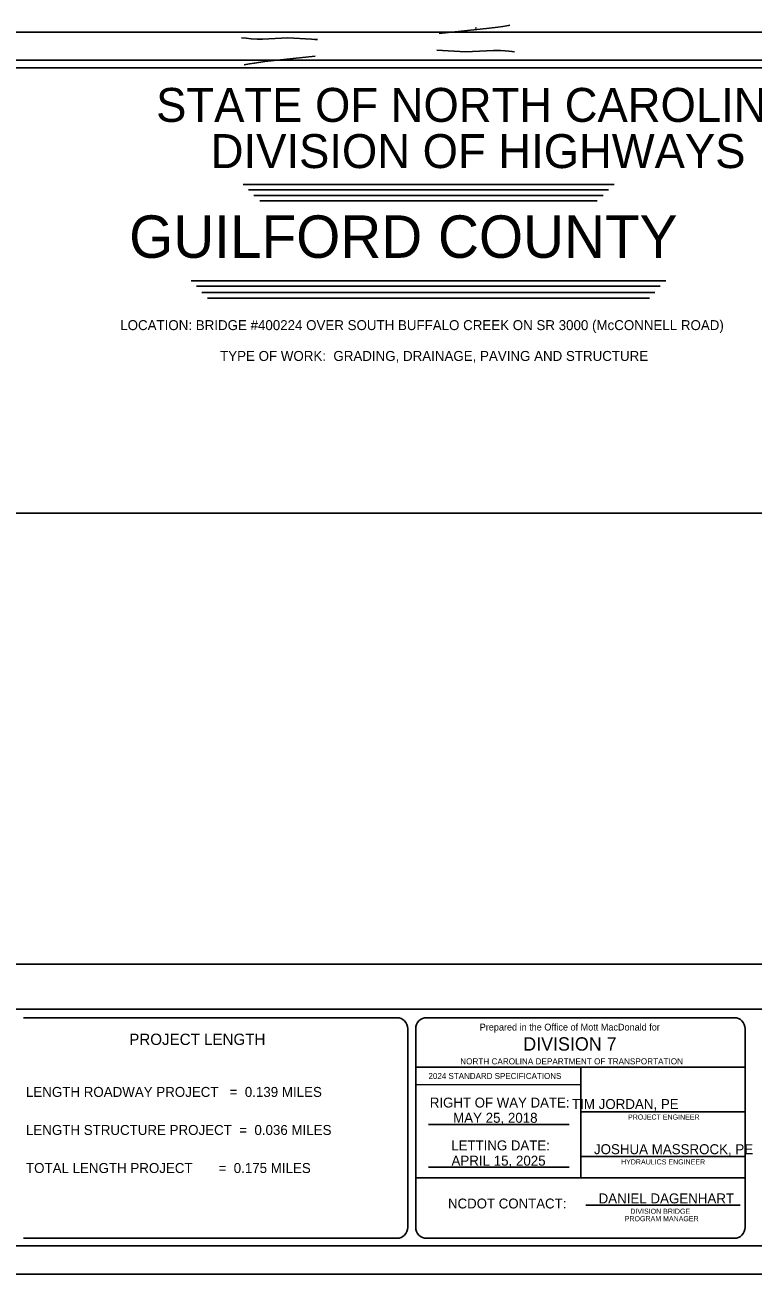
# Model space of a CAD drawing. Extents: x 2538775 to 2540487, y 826823 to 827953.
# Drawn here: x 2539375 to 2540020, y 826847 to 827953 of the extents above; entities that cross this region are included whole.
import ezdxf

# ---------------------------------------------------------------- set-up
doc = ezdxf.new("R2010")
doc.units = 0
for name, color, linetype in [('Old_Level_1', 7, 'Continuous'), ('Old_Level_23', 7, 'Continuous'), ('Old_Level_38', 7, 'Continuous'), ('Old_Level_40', 7, 'Continuous'), ('Old_Level_42', 7, 'Continuous'), ('Old_Level_62', 7, 'Continuous'), ('Old_Level_63', 7, 'Continuous'), ('Sheet Title CELL', 7, 'Continuous')]:
    doc.layers.add(name, color=color, linetype=linetype)

msp = doc.modelspace()

# ---------------------------------------------------------------- linework, layer by layer
at = {"layer": 'Old_Level_1'}
msp.add_lwpolyline([(2539256.9, 827520.8), (2540207.7, 827520.8), (2540207.7, 827121.2), (2539256.9, 827121.2)], close=True, dxfattribs=at)
at = {"layer": 'Old_Level_23'}
for points in [[(2539742.5, 827945.6), (2539787.1, 827950.3), (2539794.4, 827951.1), (2539798.8, 827951.7), (2539802.1, 827952.3), (2539803.7, 827952.6), (2539805.1, 827953)], [(2539775.5, 827950.4), (2539774.3, 827950.2)], [(2539567.2, 827941.7), (2539571.3, 827941.3), (2539575.9, 827940.9), (2539581.2, 827940.6), (2539585.7, 827940.6), (2539608.3, 827941.7), (2539629.3, 827940.4), (2539632.2, 827940.2), (2539634.6, 827940.2)], [(2539632.4, 827925.3), (2539587.8, 827920.6), (2539578.7, 827919.3), (2539574.2, 827918.5), (2539569.5, 827917.7)], [(2539809, 827929.2), (2539806.8, 827929.6), (2539804, 827929.9), (2539800.7, 827930.1), (2539796.8, 827930.3), (2539790.4, 827930.3), (2539765.7, 827929.2), (2539740.3, 827930.7)]]:
    msp.add_lwpolyline(points, dxfattribs=at)
at = {"layer": 'Old_Level_40'}
for p, q in [((2539568.6, 827811.9), (2539897.3, 827811.9)), ((2539573.4, 827807), (2539892.4, 827807)), ((2539578.2, 827802.1), (2539887.6, 827802.1)), ((2539583.5, 827797.2), (2539882.2, 827797.2)), ((2539522.5, 827726.5), (2539943.1, 827726.5)), ((2539527.4, 827721.6), (2539938.3, 827721.6)), ((2539532.2, 827716.1), (2539933.4, 827716.1)), ((2539537.1, 827711.2), (2539928.6, 827711.2)), ((2540433.1, 827081.4), (2539031.5, 827081.4)), ((2539704.9, 827073.8), (2539374.2, 827073.8)), ((2540003.8, 827073.8), (2539731.4, 827073.8)), ((2539714.5, 827064), (2539714.5, 826888.3)), ((2539721.7, 827064), (2539721.7, 826888.3)), ((2540013.5, 827064), (2540013.5, 826888.3)), ((2539721.8, 827029.9), (2540013.7, 827029.9)), ((2539867.8, 827029.8), (2539867.8, 826932)), ((2539721.8, 827014.7), (2539867.7, 827014.5)), ((2539721.6, 826932), (2540013.7, 826932)), ((2539872.2, 826907.9), (2540009, 826907.9)), ((2539704.9, 826878.5), (2539374.2, 826878.5)), ((2540003.8, 826878.5), (2539731.3, 826878.5))]:
    msp.add_line(p, q, dxfattribs=at)
for points in [[(2538967.1, 827921.8), (2540432.7, 827921.8)], [(2539031.5, 827915.2), (2540433.1, 827915.2)], [(2538967.1, 826871.8), (2540432.7, 826871.8)]]:
    msp.add_lwpolyline(points, dxfattribs=at)
for centre, major_axis, start_param, end_param in [((2539704.9, 827064), (0, 9.81), 4.711742, 6.282478), ((2539731.3, 827064), (0, 9.81), 6.282622, 7.852769), ((2540003.8, 827064), (0, 9.81), 4.712389, 6.282258), ((2539704.9, 826888.3), (0, -9.81), 6.283185, 7.853277), ((2539731.3, 826888.3), (0, 9.81), 1.569081, 3.141593), ((2540003.8, 826888.3), (0, 9.81), 3.141593, 4.712389)]:
    msp.add_ellipse(centre, major_axis=major_axis, ratio=0.985213, start_param=start_param, end_param=end_param, dxfattribs=at)
at = {"layer": 'Old_Level_62'}
msp.add_lwpolyline([(2538799.9, 826871.8), (2540449.9, 826871.8), (2540449.9, 827921.8), (2538799.9, 827921.8)], close=True, dxfattribs=at)
at = {"layer": 'Old_Level_63'}
msp.add_lwpolyline([(2538774.9, 826846.8), (2540474.9, 826846.8), (2540474.9, 827946.8), (2538774.9, 827946.8)], close=True, dxfattribs=at)
at = {"layer": 'Sheet Title CELL'}
for p, q in [((2539867.8, 826990.5), (2540013.7, 826990.5)), ((2539857.5, 826979.4), (2539732.8, 826979.4)), ((2539857.5, 826941.4), (2539732.8, 826941.4)), ((2539867.8, 826950.9), (2540013.7, 826950.8)), ((2539867.8, 826950.9), (2540013.7, 826950.8))]:
    msp.add_line(p, q, dxfattribs=at)

# ---------------------------------------------------------------- texts
at = {"layer": 'Old_Level_38'}
for s, height, rotation, p in [('GUILFORD COUNTY', 37.58, 360, (2539467.7, 827746.8)), ('      TIM JORDAN, PE      ', 8.83, 359.9851, (2539840.4, 826993)), ('MAY 25, 2018', 8.83, 359.9851, (2539754.7, 826980.8)), ('JOSHUA MASSROCK, PE', 8.83, 359.9851, (2539879.5, 826953)), ('APRIL 15, 2025', 8.83, 359.9851, (2539753.3, 826942.8))]:
    msp.add_text(s, height=height, rotation=rotation, dxfattribs=at).set_placement(p)
at = {"layer": 'Old_Level_40'}
for s, height, p in [('STATE OF NORTH CAROLINA', 30.077, (2539491.6, 827867.2)), ('DIVISION OF HIGHWAYS', 30.077, (2539540, 827826.3)), ('Prepared in the Office of Mott MacDonald for', 6.014, (2539778.3, 827062.5)), ('PROJECT LENGTH', 10.023, (2539467.8, 827049.7)), ('DIVISION 7', 11.83, (2539816.9, 827044.7)), ('NORTH CAROLINA DEPARTMENT OF TRANSPORTATION', 5.412, (2539761, 827032.5)), ('2024 STANDARD SPECIFICATIONS', 5.299, (2539732.9, 827019.6)), ('LENGTH ROADWAY PROJECT   =  0.139 MILES ', 8.83, (2539376.3, 827003.7)), ('RIGHT OF WAY DATE:', 8.769, (2539734.1, 826994.3)), ('LENGTH STRUCTURE PROJECT  =  0.036 MILES', 8.83, (2539376.3, 826970)), ('LETTING DATE:', 8.769, (2539753.1, 826956.4)), ('TOTAL LENGTH PROJECT       =  0.175 MILES', 8.83, (2539376.3, 826936.3)), ('NCDOT CONTACT:', 8.769, (2539750.2, 826904.9)), ('PROGRAM MANAGER', 4.515, (2539906.8, 826893.6)), (' DIVISION BRIDGE', 4.515, (2539910, 826900.2))]:
    msp.add_text(s, height=height, rotation=360, dxfattribs=at).set_placement(p)
at = {"layer": 'Old_Level_42'}
for s, p in [('LOCATION: BRIDGE #400224 OVER SOUTH BUFFALO CREEK ON SR 3000 (McCONNELL ROAD)', (2539459.8, 827682.8)), ('TYPE OF WORK:  GRADING, DRAINAGE, PAVING AND STRUCTURE', (2539548.3, 827655.5)), ('DANIEL DAGENHART', (2539883.6, 826909.4))]:
    msp.add_text(s, height=8.83, rotation=360, dxfattribs=at).set_placement(p)
at = {"layer": 'Sheet Title CELL'}
for s, rotation, p in [('PROJECT ENGINEER', 360, (2539909.7, 826983.6)), ('HYDRAULICS ENGINEER', 359.9851, (2539903.5, 826943.9))]:
    msp.add_text(s, height=4.515, rotation=rotation, dxfattribs=at).set_placement(p)

doc.saveas('drawing.dxf')
